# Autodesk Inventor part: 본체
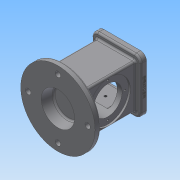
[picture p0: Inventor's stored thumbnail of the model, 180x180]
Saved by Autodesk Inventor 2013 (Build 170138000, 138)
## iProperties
Created: 2018-10
Part Number: 본체
Material: 일반
Document SubType Name: Modeling
Designer: Administrator
Density: 1 g/cm^3
Author: Administrator
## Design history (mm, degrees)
sketch "스케치2"
  geometry: L1 (-41, -46)-(41, -46); L2 (41, -46)-(41, 46); L3 (41, 46)-(-41, 46); L4 (-41, 46)-(-41, -46); L5 (-41, -46)-(41, 46); L6 (41, -46)-(-41, 46); 1 further point
  constraints: 12 end point, 2 midpoint, 2 parallel, 1 horizontal, 1 perpendicular
  dimensions: "d2" = 82 distance of L3.end L2.end; "d3" = 92 distance of L2.end L1.end
extrude "돌출1" new body sketch "스케치2" distance "d4" = 10; taper "d5" = 0 deg
sketch "스케치3"
  geometry: L1 (-33, -37)-(33, -37); L2 (33, -37)-(33, 37); L3 (33, 37)-(-33, 37); L4 (-33, 37)-(-33, -37); L5 (-33, -37)-(33, 37); L6 (33, -37)-(-33, 37); 1 further point
  constraints: 12 end point, 2 midpoint, 2 parallel, 1 horizontal, 1 perpendicular
  dimensions: "d6" = 66 distance of L3.end L2.end; "d7" = 74 distance of L2.end L1.end
extrude "돌출2" join sketch "스케치3" distance "d8" = 88; taper "d9" = 0 deg
sketch "스케치4"
  geometry: C1 r 62.5 at (0, 0); 1 further point
  constraints: 1 centre point, 1 coincident
  dimensions: "d10" = 125 diameter of C1
extrude "돌출3" join sketch "스케치4" distance "d11" = 10; taper "d12" = 0 deg
sketch "스케치5"
  geometry: L1 (-26, -26)-(26, -26); L2 (26, -26)-(26, 26); L3 (26, 26)-(-26, 26); L4 (-26, 26)-(-26, -26); L5 (-26, -26)-(26, 26); L6 (26, -26)-(-26, 26); 1 further point
  constraints: 12 end point, 2 midpoint, 2 parallel, 1 horizontal, 1 perpendicular
  dimensions: "d13" = 52 distance of L3.end L2.end; "d14" = 52 distance of L1.end L2.end
extrude "돌출4" cut sketch "스케치5" distance "d15" = 8; taper "d16" = 0 deg
sketch "스케치6"
  geometry: L1 (-22, -22)-(22, -22); L2 (22, -22)-(22, 22); L3 (22, 22)-(-22, 22); L4 (-22, 22)-(-22, -22); L5 (-22, -22)-(22, 22); L6 (22, -22)-(-22, 22); 1 further point
  constraints: 12 end point, 2 midpoint, 2 parallel, 1 horizontal, 1 perpendicular
  dimensions: "d17" = 44 distance of L3.end L2.end; "d18" = 44 distance of L2.end L1.end
extrude "돌출5" cut sketch "스케치6" distance "d19" = 74; taper "d20" = 0 deg
sketch "스케치7"
  geometry: L1 (-9, 10)-(83, 10) reference; L2 (-25.5, -98)-(99.5, -98) reference; C1 r 35 at (37, -44); 2 further points
  constraints: 1 centre point, 1 midpoint, 1 vertical alignment
  dimensions: "d21" = 70 diameter of C1; "d22" = 54 distance from line of C1.centre L2
extrude "돌출6" cut sketch "스케치7" distance "d23" = 3; taper "d24" = 0 deg
sketch "스케치8"
  geometry: C1 r 35 at (0, 0) reference; C2 r 24 at (0, 0); 1 further point
  constraints: 1 centre point, 1 coincident
  dimensions: "d25" = 48 diameter of C2
extrude "돌출7" cut sketch "스케치8" stored distance "d26" = 3; taper "d27" = 0 deg
sketch "스케치9"
  geometry: C1 r 62.5 at (0, 0) reference; C2 r 28 at (0, 0)
  constraints: 1 centre point, 1 coincident
  dimensions: "d28" = 56 diameter of C2
extrude "돌출8" cut sketch "스케치9" distance "d29" = 18; taper "d30" = -10 deg
sketch "스케치10"
  geometry: L1 (41, 46)-(-41, 46) reference; L2 (-41, 46)-(-41, -46) reference; 2 further points
  dimensions: "d31" = 10 distance from line of point (-31, 36) L1; "d32" = 10 distance from line of point (-31, 36) L2
hole "구멍1" sketch "스케치10" at (-31, 36) diameter "d33" = 3.242; stored, may be unused: countersink angle "d37" = 82 deg, drill point angle "d39" = 118 deg; dims "d34" = 4, "d35" = 3.023, "d36" = 2, "d38" = 6
sketch "스케치11" dims "d46" = 100
  geometry: C1 r 62.5 at (0, 0) reference; 2 further points
  constraints: 2 vertical alignment, 1 coincident, 2 other
hole "구멍2" sketch "스케치11" at (0, 50) diameter "d47" = 9; stored, may be unused: countersink angle "d51" = 82 deg, drill point angle "d53" = 118 deg; dims "d48" = 4, "d49" = 3.023, "d50" = 2, "d52" = 6
sketch "스케치12" dims "d57" = 58
  geometry: C1 r 35 at (0, 0) reference; 3 further points
  constraints: 2 vertical alignment, 1 coincident, 2 other
hole "구멍3" sketch "스케치12" at (0, 29) diameter "d58" = 3.242; stored, may be unused: countersink angle "d62" = 82 deg, drill point angle "d64" = 118 deg; dims "d59" = 4, "d60" = 3.023, "d61" = 2, "d63" = 6
sketch "스케치13"
  geometry: L1 (-29.5, -98)-(95.5, -98) reference; L2 (-8, 10)-(74, 10) reference; 3 further points
  constraints: 1 midpoint, 1 vertical alignment
  dimensions: "d68" = 37 distance from line of point (33, -61) L1
hole "구멍4" sketch "스케치13" at (33, -61) diameter "d69" = 4.134; stored, may be unused: countersink angle "d73" = 82 deg, drill point angle "d75" = 118 deg; dims "d70" = 20, "d71" = 3.023, "d72" = 2, "d74" = 20
sketch "스케치14"
  geometry: L1 (0, 0)-(92, 0) reference; L2 (0, 0)-(0, -10) reference; 2 further points
  constraints: 1 other
  dimensions: "d79" = 46 distance from line of point (46, -4) L2; "d80" = 4 distance from line of L1 point (46, -4)
feature "엠보싱1" sketch "스케치14" dims "d2" = 82, "d3" = 92, "d81" = 0.5, "d82" = 0
fillet "모깎기1" dims "d83" = 3
chamfer "모따기1" distance "d84" = 1; stored, may be unused: second distance "d85" = 2, angle "d86" = 45 deg
fillet "모깎기2" dims "d87" = 10
fillet "모깎기3" dims "d88" = 3
fillet "모깎기4" dims "d89" = 3
fillet "모깎기5" dims "d90" = 3
node "솔리드1"
mirror "대칭1"
pattern_linear "직사각형 패턴1" dims "d42" = 62, "d45" = 72
pattern_circular "원형 패턴1" dims angle "d55" = 360 deg
pattern_circular "원형 패턴2" dims angle "d66" = 360 deg
mirror "대칭2"
pattern_linear "직사각형 패턴2" dims "d78" = 43
